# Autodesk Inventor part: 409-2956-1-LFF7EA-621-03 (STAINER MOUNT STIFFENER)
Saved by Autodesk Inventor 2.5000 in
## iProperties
Created: 2010-06
Part Number: 409-2956-1-LFF7EA-621-03 (STAINER MOUNT STIFFENER)
Cost Center: 0 lbmass
Material: A36 STEEL PLATE
Document SubType Name: Sheet Metal
Designer: S. Boerckel
Authority: 0 in^3
Mass: 3957.41 g
Surface Area: 757.471 cm^2
Volume: 503.488 cm^3
Density: 7.86 g/cm^3
Flat Pattern Width: 6.35 cm
Flat Pattern Length: 53.34 cm
Flat Pattern Area: 338.709 cm^2
Sheet Metal Rule: 3/4"Thk
Sheet Metal Width: 21.0000 in
Sheet Metal Length: 52.5000 in^2
Description: STRAINER MOUNT STIFFENER
User Status: BURN
SaveDate: 2008-01-15
SaveTime: 10:24
FileName: Sheet Metal
Wide: =<Flat Pattern Width>cm
Length: =<Flat Pattern Length>cm
Thickness: 0.7500 in
SMR: =<Sheet Metal Rule> - <Material>
Author: S. Boerckel
Revision Number: 0
Subject: DEMIN WATER FORWARDING PUMP SKID-7EA
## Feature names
1. Plate1
